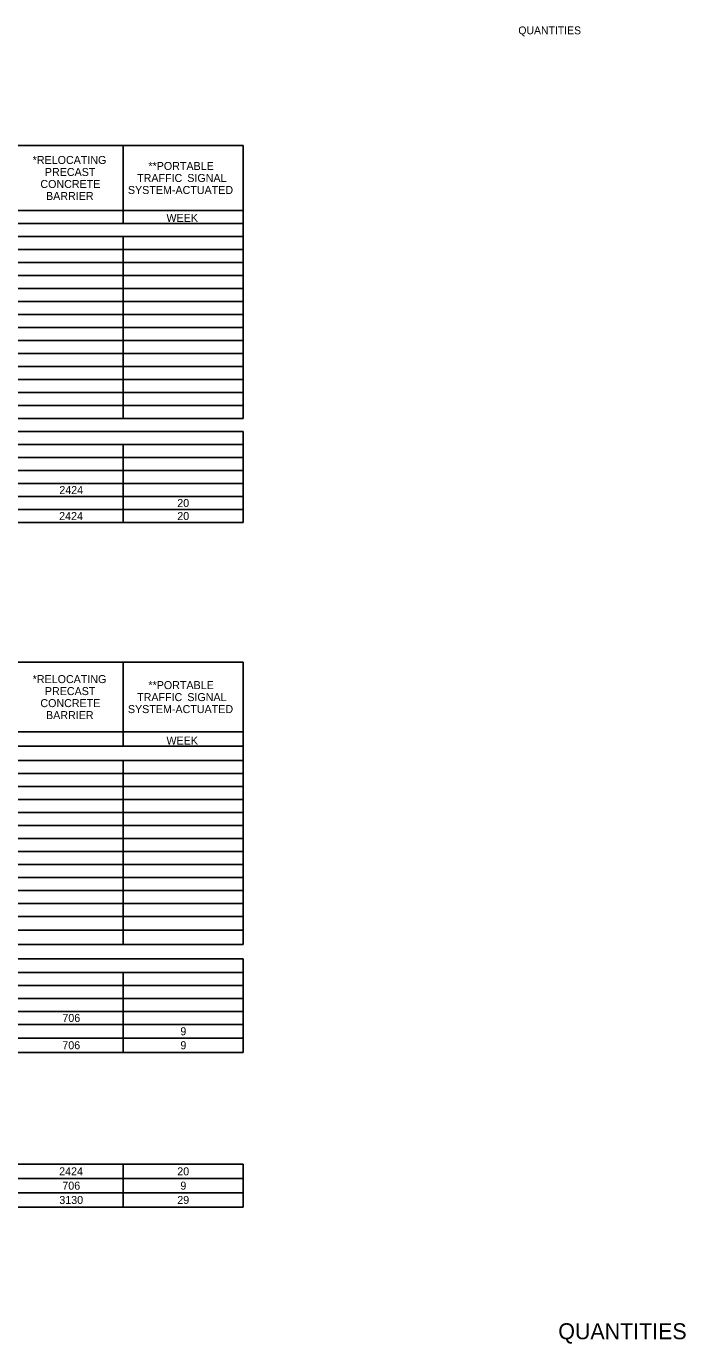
# Model space of a CAD drawing. Extents: x 544478 to 1930787, y -1948294 to 596640.
# Drawn here: x 545294 to 545789, y -1947044 to -1946056 of the extents above; entities that cross this region are included whole.
import ezdxf

# ---------------------------------------------------------------- set-up
doc = ezdxf.new("R2010")
doc.units = 0
for name, color, linetype in [('Default', 7, 'Continuous'), ('R_Border', 7, 'Continuous'), ('R_Border Prem', 7, 'Continuous')]:
    doc.layers.add(name, color=color, linetype=linetype)

msp = doc.modelspace()

# ---------------------------------------------------------------- linework, layer by layer
at = {"layer": 'Default'}
for p, q in [((544484.28, -1946145.77), (545456.84, -1946145.77)), ((545366.65, -1946204.27), (545366.65, -1946145.77)), ((545456.84, -1946350.52), (545456.84, -1946145.77)), ((545010.78, -1946194.52), (545456.84, -1946194.52)), ((544484.28, -1946204.27), (545456.84, -1946204.27)), ((544952.76, -1946204.27), (545456.84, -1946204.27)), ((544484.28, -1946214.02), (545456.84, -1946214.02)), ((545366.65, -1946350.52), (545366.65, -1946214.02)), ((545366.65, -1946350.52), (545366.65, -1946214.02)), ((544484.28, -1946223.77), (545456.84, -1946223.77)), ((544484.28, -1946233.52), (545456.84, -1946233.52)), ((544484.28, -1946243.27), (545456.84, -1946243.27)), ((544484.28, -1946253.02), (545456.84, -1946253.02)), ((544484.28, -1946262.77), (545456.84, -1946262.77)), ((544484.28, -1946272.52), (545456.84, -1946272.52)), ((544484.28, -1946282.27), (545456.84, -1946282.27)), ((544484.28, -1946292.02), (545456.84, -1946292.02)), ((544484.28, -1946301.77), (545456.84, -1946301.77)), ((544484.28, -1946311.52), (545456.84, -1946311.52)), ((544484.28, -1946321.27), (545456.84, -1946321.27)), ((544484.28, -1946331.02), (545456.84, -1946331.02)), ((544484.28, -1946340.77), (545456.84, -1946340.77)), ((545366.65, -1946340.77), (545456.84, -1946340.77)), ((544484.28, -1946350.52), (545456.84, -1946350.52)), ((544484.28, -1946360.27), (545456.84, -1946360.27)), ((544534.49, -1946360.27), (545456.84, -1946360.27)), ((545456.84, -1946428.52), (545456.84, -1946360.27)), ((544484.28, -1946370.02), (545456.84, -1946370.02)), ((545366.65, -1946389.52), (545366.65, -1946370.02)), ((545366.65, -1946428.52), (545366.65, -1946370.02)), ((544484.28, -1946379.77), (545456.84, -1946379.77)), ((544484.28, -1946389.52), (545456.84, -1946389.52)), ((545211.63, -1946399.27), (545456.84, -1946399.27)), ((545366.65, -1946428.52), (545366.65, -1946399.27)), ((544484.28, -1946409.02), (545456.84, -1946409.02)), ((544484.28, -1946418.77), (545456.84, -1946418.77)), ((544484.28, -1946428.52), (545456.84, -1946428.52)), ((544484.28, -1946533.34), (545456.84, -1946533.34)), ((545366.65, -1946596.22), (545366.65, -1946533.34)), ((545456.84, -1946744.91), (545456.84, -1946533.34)), ((545010.78, -1946585.5), (545456.84, -1946585.5)), ((544484.28, -1946596.22), (545456.84, -1946596.22)), ((544952.76, -1946596.22), (545456.84, -1946596.22)), ((544484.28, -1946606.95), (545456.84, -1946606.95)), ((545366.65, -1946694.7), (545366.65, -1946606.95)), ((545366.65, -1946744.91), (545366.65, -1946606.95)), ((544484.28, -1946616.7), (545456.84, -1946616.7)), ((544484.28, -1946626.45), (545456.84, -1946626.45)), ((544484.28, -1946636.2), (545456.84, -1946636.2)), ((544484.28, -1946645.95), (545456.84, -1946645.95)), ((544484.28, -1946655.7), (545456.84, -1946655.7)), ((544484.28, -1946665.45), (545456.84, -1946665.45)), ((544484.28, -1946675.2), (545456.84, -1946675.2)), ((544484.28, -1946684.95), (545456.84, -1946684.95)), ((544484.28, -1946694.7), (545456.84, -1946694.7)), ((544484.28, -1946704.45), (545456.84, -1946704.45)), ((544484.28, -1946714.2), (545456.84, -1946714.2)), ((544484.28, -1946723.95), (545456.84, -1946723.95)), ((544484.28, -1946734.19), (545456.84, -1946734.19)), ((544484.28, -1946734.19), (545456.84, -1946734.19)), ((544484.28, -1946744.91), (545456.84, -1946744.91)), ((545366.65, -1946744.91), (545456.84, -1946744.91)), ((544484.28, -1946755.64), (545456.84, -1946755.64)), ((544484.28, -1946755.64), (545456.84, -1946755.64)), ((545456.84, -1946825.84), (545456.84, -1946755.64)), ((544484.28, -1946765.87), (545456.84, -1946765.87)), ((545366.65, -1946785.37), (545366.65, -1946765.87)), ((545366.65, -1946825.84), (545366.65, -1946765.87)), ((545211.63, -1946775.62), (545456.84, -1946775.62)), ((544484.28, -1946785.37), (545456.84, -1946785.37)), ((545211.63, -1946795.12), (545456.84, -1946795.12)), ((545366.65, -1946825.84), (545366.65, -1946795.12)), ((544484.28, -1946804.87), (545456.84, -1946804.87)), ((544484.28, -1946815.11), (545456.84, -1946815.11)), ((544484.28, -1946825.84), (545456.84, -1946825.84)), ((544484.28, -1946909.69), (545456.84, -1946909.69)), ((544484.28, -1946909.69), (545456.84, -1946909.69)), ((545366.65, -1946941.86), (545366.65, -1946909.69)), ((545456.84, -1946941.86), (545456.84, -1946909.69)), ((544484.28, -1946920.41), (545456.84, -1946920.41)), ((544484.28, -1946931.14), (545456.84, -1946931.14)), ((544484.28, -1946941.86), (545456.84, -1946941.86))]:
    msp.add_line(p, q, dxfattribs=at)

# ---------------------------------------------------------------- texts
for s, p in [('*RELOCATING', (545298.8, -1946159.65)), ('PRECAST', (545307.95, -1946168.65)), ('**PORTABLE', (545385.63, -1946164.15)), ('CONCRETE', (545304.58, -1946177.65)), ('TRAFFIC', (545377.15, -1946173.15)), (' SIGNAL', (545412.58, -1946173.15)), ('BARRIER', (545308.82, -1946186.65)), ('SYSTEM-ACTUATED', (545370.26, -1946182.15)), ('WEEK', (545399.17, -1946203.07)), ('2424', (545318.78, -1946407.15)), ('20', (545407.29, -1946416.9)), ('2424', (545318.67, -1946426.65)), ('20', (545407.29, -1946426.65)), ('*RELOCATING', (545298.8, -1946548.92)), ('**PORTABLE', (545385.63, -1946553.42)), ('PRECAST', (545307.95, -1946557.92)), ('TRAFFIC', (545377.15, -1946562.42)), (' SIGNAL', (545412.58, -1946562.42)), ('CONCRETE', (545304.58, -1946566.92)), ('SYSTEM-ACTUATED', (545370.26, -1946571.42)), ('BARRIER', (545308.82, -1946575.92)), ('WEEK', (545399.17, -1946595.02)), ('706', (545321.09, -1946803)), ('9', (545409.6, -1946812.99)), ('706', (545321.05, -1946823.47)), ('9', (545409.61, -1946823.47)), ('2424', (545318.67, -1946918.05)), ('20', (545407.29, -1946918.05)), ('706', (545321.05, -1946928.77)), ('9', (545409.61, -1946928.77)), ('3130', (545318.78, -1946939.5)), ('29', (545407.28, -1946939.5))]:
    msp.add_text(s, height=6, dxfattribs=at).set_placement(p)
at = {"layer": 'R_Border'}
msp.add_text('QUANTITIES', height=12, rotation=360, dxfattribs=at).set_placement((545693.16, -1947040.95))
at = {"layer": 'R_Border Prem'}
msp.add_text('QUANTITIES', height=5.862, rotation=360, dxfattribs=at).set_placement((545663.18, -1946062.39))

doc.saveas('drawing.dxf')
